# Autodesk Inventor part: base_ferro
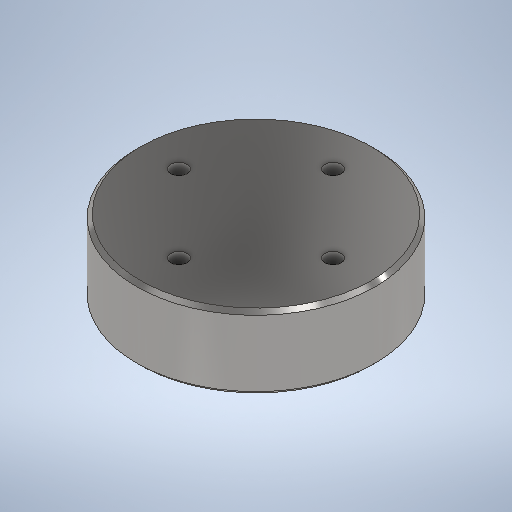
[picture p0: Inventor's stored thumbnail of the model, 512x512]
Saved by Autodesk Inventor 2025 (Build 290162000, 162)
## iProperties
Created: 2026-01
Part Number: base_ferro
Material: Acciaio
Document SubType Name: Modeling
Designer: Ryzen5700u
Density: 7.85 g/cm^3
Appearance: Acciaio - Lucido
Mass: 7039.17 g
Surface Area: 726.938 cm^2
Volume: 896.709 cm^3
Author: Ryzen5700u
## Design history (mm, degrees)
sketch "Schizzo1"
  geometry: C1 r 50 at (0, 0); 1 further point
  constraints: 1 centre point, 1 coincident
  dimensions: "d0" = 100 diameter of C1
extrude "Estrusione1" new body sketch "Schizzo1" distance "d1" = 40; taper "d2" = 0 deg
sketch "Schizzo3"
  geometry: L1 (0, 0)-(42, 0)
  constraints: 2 end point, 1 horizontal
  dimensions: "d14" = 42 distance of L1.start L1.end
hole "Foro2" sketch "Schizzo3" at (42, 0) diameter "d15" = 5.3; stored, may be unused: countersink angle "d19" = 90 deg, drill point angle "d21" = 118 deg; dims "d16" = 6, "d17" = 9, "d18" = 15, "d20" = 8
pattern_circular "Serie circolare2" dims angle "d23" = 360 deg
sketch "Schizzo4"
  geometry: C1 r 65 at (0, 0); C2 r 50 at (0, 0) reference; 1 further point
  constraints: 1 centre point, 1 coincident
  dimensions: "d25" = 130 diameter of C1
extrude "Estrusione2" join sketch "Schizzo4" stored distance "d26" = 10; taper "d27" = 0 deg
chamfer "Smusso1" distance "d28" = 2; stored, may be unused: second distance "d29" = 2, angle "d30" = 45 deg
node "Solido1"
